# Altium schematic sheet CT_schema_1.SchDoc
size 531 x 258 mm
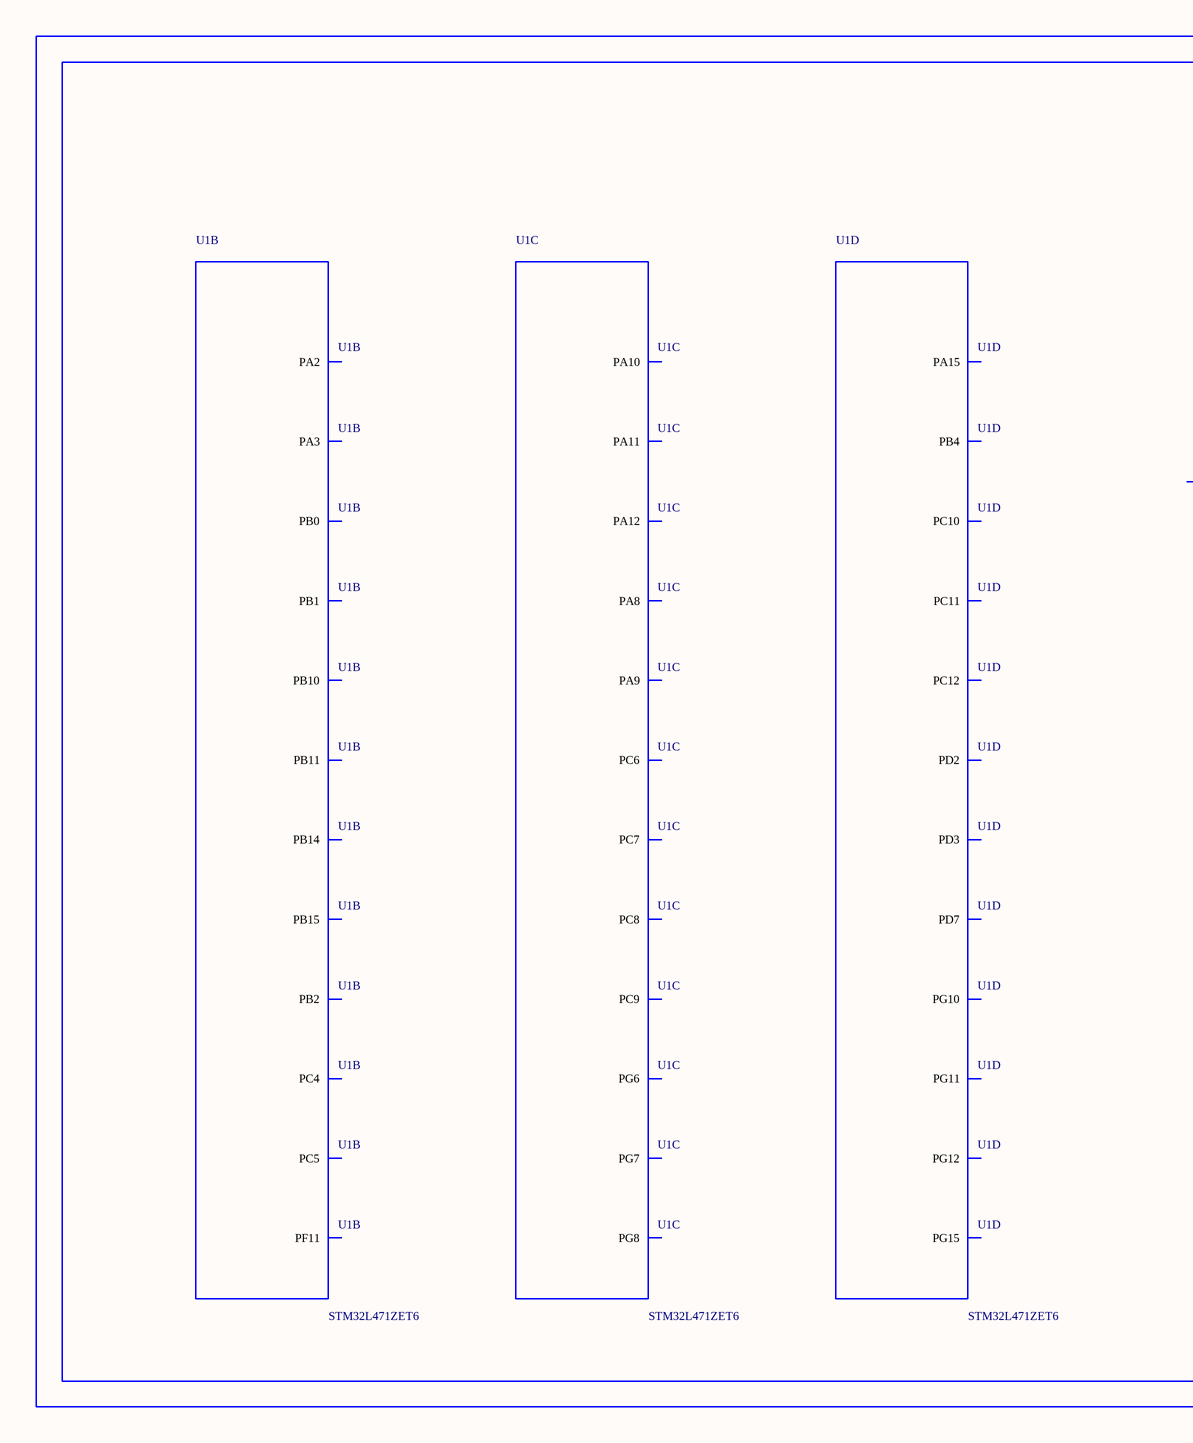
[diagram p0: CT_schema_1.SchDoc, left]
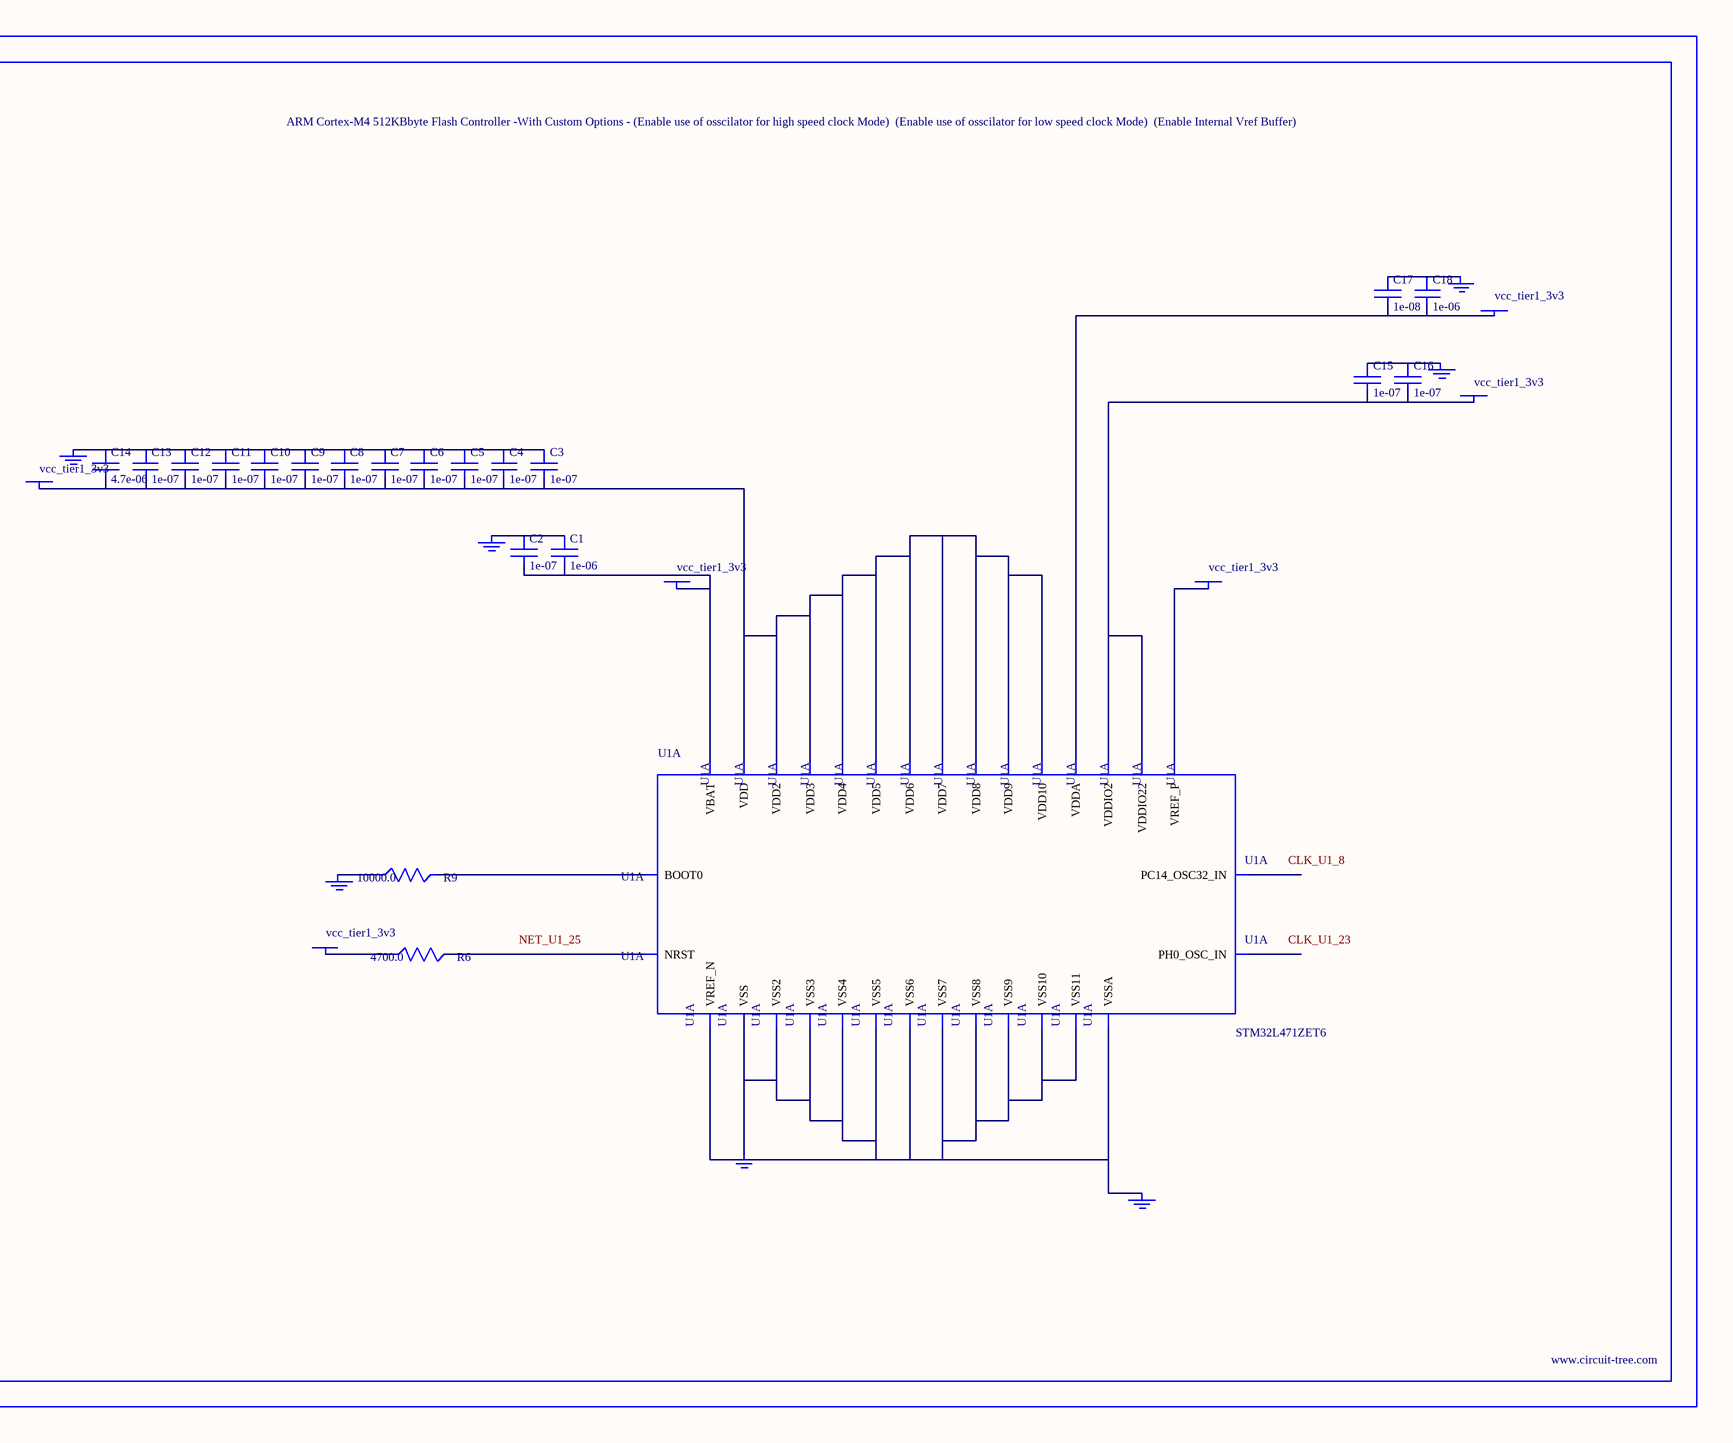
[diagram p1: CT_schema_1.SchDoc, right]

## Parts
BORDER0  (no value)
C1  1e-06  [C0603]
C2  1e-07  [C0603]
C3  1e-07  [C0603]
C4  1e-07  [C0603]
C5  1e-07  [C0603]
C6  1e-07  [C0603]
C7  1e-07  [C0603]
C8  1e-07  [C0603]
C9  1e-07  [C0603]
C10  1e-07  [C0603]
C11  1e-07  [C0603]
C12  1e-07  [C0603]
C13  1e-07  [C0603]
C14  4.7e-06  [C0603]
C15  1e-07  [C0603]
C16  1e-07  [C0603]
C17  1e-08  [C0603]
C18  1e-06  [C0603]
GND_INSTANCE_0_0  (no value)
GND_INSTANCE_0_1  (no value)
GND_INSTANCE_0_2  (no value)
GND_INSTANCE_0_3  (no value)
GND_INSTANCE_0_4  (no value)
GND_INSTANCE_0_5  (no value)
GND_INSTANCE_0_6  (no value)
POWER_INSTANCE_0_0  vcc_tier1_3v3
POWER_INSTANCE_0_1  vcc_tier1_3v3
POWER_INSTANCE_0_2  vcc_tier1_3v3
POWER_INSTANCE_0_3  vcc_tier1_3v3
POWER_INSTANCE_0_4  vcc_tier1_3v3
POWER_INSTANCE_0_5  vcc_tier1_3v3
R6  4700.0  [R0603]
R9  10000.0  [R0603]
U1  STM32L471ZET6  [LQFP144]  (parts A,B,C,D of 13)

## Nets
NetC1_1: C1.1 C2.1 GND_INSTANCE_0_0.0(GND)
NetC1_2: C1.2 C2.2 POWER_INSTANCE_0_0.0(PWR) U1.6(VBAT)
NetC3_1: C3.1 C4.1 C5.1 C6.1 C7.1 C8.1 C9.1 C10.1 C11.1 C12.1 C13.1 C14.1 GND_INSTANCE_0_1.0(GND)
NetC3_2: C3.2 C4.2 C5.2 C6.2 C7.2 C8.2 C9.2 C10.2 C11.2 C12.2 C13.2 C14.2 POWER_INSTANCE_0_1.0(PWR) U1.17(VDD) U1.39(VDD2) U1.52(VDD3) U1.62(VDD4) U1.72(VDD5) U1.84(VDD6) U1.106(VDD7) U1.108(VDD8) U1.121(VDD9) U1.144(VDD10)
NetC15_1: C15.1 C16.1 GND_INSTANCE_0_4.0(GND)
NetC15_2: C15.2 C16.2 POWER_INSTANCE_0_4.0(PWR) U1.95(VDDIO2) U1.131(VDDIO22)
NetC17_1: C17.1 C18.1 GND_INSTANCE_0_3.0(GND)
NetC17_2: C17.2 C18.2 POWER_INSTANCE_0_3.0(PWR) U1.33(VDDA)
NetGND_INSTANCE_0_2_0: GND_INSTANCE_0_2.0(GND) GND_INSTANCE_0_6.0(GND) U1.16(VSS) U1.30(VSSA) U1.31(VREF_N) U1.38(VSS2) U1.51(VSS3) U1.61(VSS4) U1.71(VSS5) U1.83(VSS6) U1.94(VSS7) U1.107(VSS8) U1.120(VSS9) U1.130(VSS10) U1.143(VSS11)
NetGND_INSTANCE_0_5_0: GND_INSTANCE_0_5.0(GND) R9.1
NetPOWER_INSTANCE_0_2_0: POWER_INSTANCE_0_2.0(PWR) U1.32(VREF_P)
NetPOWER_INSTANCE_0_5_0: POWER_INSTANCE_0_5.0(PWR) R6.1
NetR6_2: R6.2 U1.25(NRST)
NetR9_2: R9.2 U1.138(BOOT0)

Not connected (* = marked no-connect by the designer): U1 8(PC14_OSC32_IN) 23(PH0_OSC_IN) 36(PA2) 37(PA3) 44(PC4) 45(PC5) 46(PB0) 47(PB1) 48(PB2) 49(PF11) 69(PB10) 70(PB11) 75(PB14) 76(PB15) 91(PG6) 92(PG7) 93(PG8) 96(PC6) 97(PC7) 98(PC8) 99(PC9) 100(PA8) 101(PA9) 102(PA10) 103(PA11) 104(PA12) 110(PA15) 111(PC10) 112(PC11) 113(PC12) 116(PD2) 117(PD3) 123(PD7) 125(PG10) 126(PG11) 127(PG12) 132(PG15) 134(PB4)

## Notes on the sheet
- Labels drawn without touching a wire or pin: CLK_U1_8, CLK_U1_23, NET_U1_25

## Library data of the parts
BORDER0 = BORDER_PAGE0
C1 C18 = C0603C105K3RACTU
C2-C13 C15 C16 = 06035C104K4Z2A
C14 = GRM188R6YA475KE15D
C17 = 06035C103K4Z2A
GND_INSTANCE_0_0-GND_INSTANCE_0_6 = GND
POWER_INSTANCE_0_0-POWER_INSTANCE_0_5 = PWR
R6 = RC0603JR-074K7L
R9 = RC0603JR-0710KL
